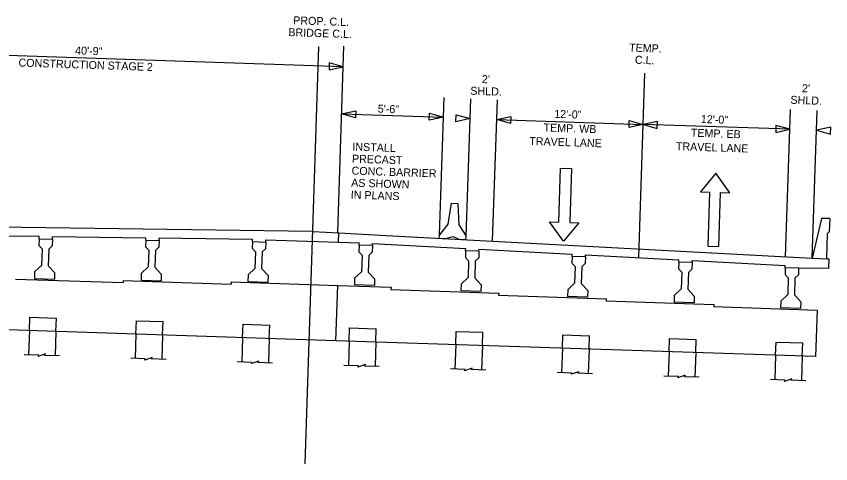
# Model space of a CAD drawing. Extents: x 977258 to 978774, y 1525947 to 1526932.
# Drawn here: x 977645 to 978256, y 1526136 to 1526472 of the extents above; entities that cross this region are included whole.
import ezdxf

# ---------------------------------------------------------------- set-up
doc = ezdxf.new("R2010")
doc.units = 0
for name, color, linetype in [('B_County and Route', 7, 'Continuous'), ('BDR_Plan Profile Grid 1', 7, 'Continuous'), ('BDR_Plan Profile Grid 5', 7, 'Continuous'), ('BDR_Plan Profile Grid 6', 7, 'Continuous'), ('Default', 7, 'Continuous'), ('R_Border', 7, 'Continuous'), ('R_MOT', 7, 'Continuous'), ('STAMP_PP', 7, 'Continuous')]:
    doc.layers.add(name, color=color, linetype=linetype)

msp = doc.modelspace()

# ---------------------------------------------------------------- linework, layer by layer
at = {"layer": 'B_County and Route'}
for p, q in [((977861.48, 1526136.32), (977871.91, 1526449.32)), ((978111.78, 1526291.34), (978116.39, 1526429.43))]:
    msp.add_line(p, q, dxfattribs=at)
at = {"layer": 'BDR_Plan Profile Grid 1'}
for p, q in [((977661.69, 1526217.73), (977650.75, 1526218.1)), ((977666.88, 1526218.68), (977661.27, 1526216.79)), ((977661.27, 1526216.79), (977661.69, 1526217.73)), ((977666.18, 1526217.58), (977666.88, 1526218.68)), ((977677.24, 1526217.21), (977666.18, 1526217.58)), ((977741.64, 1526215.07), (977730.71, 1526215.43)), ((977746.84, 1526216.01), (977741.23, 1526214.12)), ((977741.23, 1526214.12), (977741.64, 1526215.07)), ((977746.14, 1526214.92), (977746.84, 1526216.01)), ((977757.2, 1526214.55), (977746.14, 1526214.92)), ((977821.6, 1526212.4), (977810.67, 1526212.76)), ((977826.79, 1526213.35), (977821.18, 1526211.45)), ((977821.18, 1526211.45), (977821.6, 1526212.4)), ((977826.09, 1526212.25), (977826.79, 1526213.35)), ((977837.15, 1526211.88), (977826.09, 1526212.25))]:
    msp.add_line(p, q, dxfattribs=at)
at = {"layer": 'BDR_Plan Profile Grid 5'}
for p, q in [((977867.29, 1526310.65), (977492.25, 1526315.66)), ((978248.66, 1526320.45), (978241.83, 1526290.66)), ((978254.91, 1526320.24), (978248.66, 1526320.45)), ((978254.91, 1526320.24), (978254.57, 1526310.25)), ((977867.29, 1526310.65), (977886.74, 1526309.62)), ((977886.74, 1526309.62), (977922.22, 1526307.72)), ((978252.65, 1526290.08), (978253.28, 1526309.04)), ((978254.57, 1526310.25), (978253.28, 1526309.04)), ((977662.04, 1526306.73), (977592.03, 1526307.66)), ((977661.99, 1526305.16), (977661.82, 1526300.16)), ((977661.99, 1526305.16), (977661.82, 1526300.16)), ((977661.99, 1526305.16), (977662.04, 1526306.73)), ((977661.99, 1526305.16), (977671.98, 1526304.83)), ((977661.99, 1526305.16), (977671.98, 1526304.83)), ((977671.98, 1526304.83), (977671.82, 1526299.83)), ((977671.98, 1526304.83), (977671.82, 1526299.83)), ((977671.98, 1526304.83), (977671.82, 1526299.83)), ((977671.98, 1526304.83), (977671.82, 1526299.83)), ((977671.98, 1526304.83), (977672.04, 1526306.59)), ((977742.05, 1526305.66), (977672.04, 1526306.59)), ((977742, 1526304.09), (977741.83, 1526299.1)), ((977742, 1526304.09), (977741.83, 1526299.1)), ((977742, 1526304.09), (977742.05, 1526305.66)), ((977742, 1526304.09), (977751.99, 1526303.76)), ((977742, 1526304.09), (977751.99, 1526303.76)), ((977751.99, 1526303.76), (977751.83, 1526298.76)), ((977751.99, 1526303.76), (977751.83, 1526298.76)), ((977751.99, 1526303.76), (977751.83, 1526298.76)), ((977751.99, 1526303.76), (977751.83, 1526298.76)), ((977751.99, 1526303.76), (977752.05, 1526305.53)), ((977822.06, 1526304.59), (977752.05, 1526305.53)), ((977822.01, 1526303.03), (977821.84, 1526298.03)), ((977822.01, 1526303.03), (977821.84, 1526298.03)), ((977822.01, 1526303.03), (977822.06, 1526304.59)), ((977822.01, 1526303.03), (977832, 1526302.69)), ((977822.01, 1526303.03), (977832, 1526302.69)), ((977832, 1526302.69), (977831.84, 1526297.7)), ((977832, 1526302.69), (977831.84, 1526297.7)), ((977832, 1526302.69), (977831.84, 1526297.7)), ((977832, 1526302.69), (977831.84, 1526297.7)), ((977832, 1526302.69), (977832.06, 1526304.46)), ((977832.06, 1526304.46), (977886.51, 1526302.64)), ((977886.51, 1526302.64), (977902.02, 1526302.12)), ((977922.22, 1526307.72), (978241.83, 1526290.66)), ((977661.82, 1526300.16), (977664.24, 1526297.58)), ((977661.82, 1526300.16), (977664.24, 1526297.58)), ((977664.24, 1526297.58), (977663.82, 1526285.09)), ((977664.24, 1526297.58), (977663.82, 1526285.09)), ((977669.24, 1526297.41), (977668.82, 1526284.92)), ((977669.24, 1526297.41), (977668.82, 1526284.92)), ((977671.82, 1526299.83), (977669.24, 1526297.41)), ((977671.82, 1526299.83), (977669.24, 1526297.41)), ((977741.83, 1526299.1), (977744.25, 1526296.51)), ((977741.83, 1526299.1), (977744.25, 1526296.51)), ((977744.25, 1526296.51), (977743.83, 1526284.02)), ((977744.25, 1526296.51), (977743.83, 1526284.02)), ((977749.25, 1526296.35), (977748.83, 1526283.85)), ((977749.25, 1526296.35), (977748.83, 1526283.85)), ((977751.83, 1526298.76), (977749.25, 1526296.35)), ((977751.83, 1526298.76), (977749.25, 1526296.35)), ((977821.84, 1526298.03), (977824.26, 1526295.45)), ((977821.84, 1526298.03), (977824.26, 1526295.45)), ((977831.84, 1526297.7), (977829.25, 1526295.28)), ((977831.84, 1526297.7), (977829.25, 1526295.28)), ((977901.97, 1526300.36), (977901.8, 1526295.36)), ((977901.97, 1526300.36), (977901.8, 1526295.36)), ((977901.97, 1526300.36), (977902.02, 1526302.12)), ((977911.96, 1526300.03), (977901.97, 1526300.36)), ((977911.96, 1526300.03), (977911.79, 1526295.03)), ((977911.96, 1526300.03), (977912.01, 1526301.59)), ((977912.01, 1526301.59), (977981.93, 1526297.86)), ((977981.87, 1526296.09), (977981.93, 1526297.86)), ((977991.86, 1526295.76), (977991.91, 1526297.33)), ((977991.91, 1526297.33), (978061.83, 1526293.59)), ((977824.26, 1526295.45), (977823.84, 1526282.95)), ((977824.26, 1526295.45), (977823.84, 1526282.95)), ((977829.25, 1526295.28), (977828.84, 1526282.79)), ((977829.25, 1526295.28), (977828.84, 1526282.79)), ((977901.8, 1526295.36), (977904.21, 1526292.78)), ((977904.21, 1526292.78), (977903.8, 1526280.29)), ((977909.21, 1526292.61), (977908.8, 1526280.12)), ((977911.79, 1526295.03), (977909.21, 1526292.61)), ((977981.87, 1526296.09), (977981.7, 1526291.1)), ((977981.87, 1526296.09), (977981.7, 1526291.1)), ((977981.7, 1526291.1), (977984.12, 1526288.51)), ((977991.86, 1526295.76), (977981.87, 1526296.09)), ((977991.7, 1526290.76), (977989.11, 1526288.35)), ((977991.86, 1526295.76), (977991.7, 1526290.76)), ((978061.77, 1526291.83), (978061.6, 1526286.83)), ((978061.77, 1526291.83), (978061.6, 1526286.83)), ((978061.77, 1526291.83), (978061.83, 1526293.59)), ((978071.76, 1526291.5), (978061.77, 1526291.83)), ((978071.76, 1526291.5), (978071.6, 1526286.5)), ((978071.76, 1526291.5), (978071.82, 1526293.06)), ((978071.82, 1526293.06), (978141.73, 1526289.33)), ((978252.65, 1526290.08), (978254.31, 1526289.99)), ((977658.66, 1526280.26), (977663.82, 1526285.09)), ((977658.66, 1526280.26), (977663.82, 1526285.09)), ((977673.65, 1526279.76), (977668.82, 1526284.92)), ((977673.65, 1526279.76), (977668.82, 1526284.92)), ((977738.67, 1526279.19), (977743.83, 1526284.02)), ((977738.67, 1526279.19), (977743.83, 1526284.02)), ((977984.12, 1526288.51), (977983.7, 1526276.02)), ((977989.11, 1526288.35), (977988.7, 1526275.86)), ((978061.6, 1526286.83), (978064.02, 1526284.25)), ((978064.02, 1526284.25), (978063.6, 1526271.76)), ((978069.02, 1526284.08), (978068.6, 1526271.59)), ((978071.6, 1526286.5), (978069.02, 1526284.08)), ((978141.67, 1526287.56), (978141.51, 1526282.57)), ((978141.67, 1526287.56), (978141.51, 1526282.57)), ((978141.67, 1526287.56), (978141.73, 1526289.33)), ((978151.67, 1526287.23), (978141.67, 1526287.56)), ((978151.67, 1526287.23), (978151.5, 1526282.23)), ((978151.67, 1526287.23), (978151.72, 1526288.8)), ((978151.72, 1526288.8), (978221.63, 1526285.06)), ((978221.57, 1526283.3), (978221.63, 1526285.06)), ((978254.31, 1526289.99), (978254.07, 1526282.71)), ((977658.66, 1526280.26), (977658.49, 1526275.26)), ((977658.66, 1526280.26), (977658.49, 1526275.26)), ((977673.65, 1526279.76), (977673.48, 1526274.76)), ((977673.65, 1526279.76), (977673.48, 1526274.76)), ((977738.67, 1526279.19), (977738.5, 1526274.19)), ((977738.67, 1526279.19), (977738.5, 1526274.19)), ((977753.66, 1526278.69), (977748.83, 1526283.85)), ((977753.66, 1526278.69), (977748.83, 1526283.85)), ((977753.66, 1526278.69), (977753.49, 1526273.69)), ((977753.66, 1526278.69), (977753.49, 1526273.69)), ((977818.68, 1526278.12), (977818.51, 1526273.13)), ((977818.68, 1526278.12), (977818.51, 1526273.13)), ((977818.68, 1526278.12), (977823.84, 1526282.95)), ((977818.68, 1526278.12), (977823.84, 1526282.95)), ((977833.67, 1526277.62), (977828.84, 1526282.79)), ((977833.67, 1526277.62), (977828.84, 1526282.79)), ((977898.63, 1526275.46), (977903.8, 1526280.29)), ((977913.63, 1526274.96), (977908.8, 1526280.12)), ((978141.51, 1526282.57), (978143.92, 1526279.98)), ((978143.92, 1526279.98), (978143.5, 1526267.49)), ((978148.92, 1526279.82), (978148.5, 1526267.32)), ((978151.5, 1526282.23), (978148.92, 1526279.82)), ((978221.57, 1526283.3), (978221.41, 1526278.3)), ((978221.57, 1526283.3), (978221.41, 1526278.3)), ((978221.41, 1526278.3), (978223.82, 1526275.72)), ((978231.57, 1526282.96), (978221.57, 1526283.3)), ((978231.4, 1526277.97), (978228.82, 1526275.55)), ((978231.57, 1526282.96), (978231.4, 1526277.97)), ((978254.07, 1526282.71), (978231.57, 1526282.96)), ((977644.31, 1526274.9), (977725.1, 1526272.21)), ((977658.49, 1526275.26), (977673.48, 1526274.76)), ((977658.49, 1526275.26), (977673.48, 1526274.76)), ((977725.15, 1526273.8), (977725.1, 1526272.21)), ((977725.15, 1526273.8), (977805.94, 1526271.11)), ((977738.5, 1526274.19), (977753.49, 1526273.69)), ((977738.5, 1526274.19), (977753.49, 1526273.69)), ((977805.99, 1526272.71), (977805.94, 1526271.11)), ((977805.99, 1526272.71), (977885.94, 1526270.04)), ((977818.51, 1526273.13), (977833.5, 1526272.63)), ((977818.51, 1526273.13), (977833.5, 1526272.63)), ((977833.67, 1526277.62), (977833.5, 1526272.63)), ((977833.67, 1526277.62), (977833.5, 1526272.63)), ((977898.63, 1526275.46), (977898.47, 1526270.46)), ((977913.63, 1526274.96), (977913.46, 1526269.96)), ((977978.54, 1526271.19), (977983.7, 1526276.02)), ((977993.53, 1526270.69), (977988.7, 1526275.86)), ((978058.44, 1526266.93), (978063.6, 1526271.76)), ((978223.82, 1526275.72), (978223.41, 1526263.23)), ((978228.82, 1526275.55), (978228.4, 1526263.06)), ((977884.56, 1526228.67), (977885.94, 1526270.04)), ((977885.94, 1526270.04), (977925.92, 1526268.71)), ((977913.46, 1526269.96), (977898.47, 1526270.46)), ((977925.92, 1526268.71), (977925.87, 1526267.11)), ((977925.87, 1526267.11), (978006.66, 1526264.42)), ((977978.54, 1526271.19), (977978.37, 1526266.19)), ((977993.36, 1526265.69), (977978.37, 1526266.19)), ((977993.53, 1526270.69), (977993.36, 1526265.69)), ((978058.44, 1526266.93), (978058.27, 1526261.93)), ((978073.43, 1526266.43), (978068.6, 1526271.59)), ((978073.43, 1526266.43), (978073.26, 1526261.43)), ((978138.34, 1526262.66), (978143.5, 1526267.49)), ((978153.33, 1526262.16), (978148.5, 1526267.32)), ((978006.66, 1526264.42), (978006.6, 1526262.82)), ((978006.6, 1526262.82), (978087.39, 1526260.12)), ((978073.26, 1526261.43), (978058.27, 1526261.93)), ((978087.39, 1526260.12), (978087.34, 1526258.52)), ((978138.34, 1526262.66), (978138.17, 1526257.66)), ((978153.33, 1526262.16), (978153.17, 1526257.16)), ((978218.24, 1526258.39), (978223.41, 1526263.23)), ((978233.23, 1526257.89), (978228.4, 1526263.06)), ((978087.34, 1526258.52), (978168.13, 1526255.83)), ((978153.17, 1526257.16), (978138.17, 1526257.66)), ((978168.13, 1526255.83), (978168.07, 1526254.23)), ((978168.07, 1526254.23), (978245.53, 1526251.65)), ((978218.24, 1526258.39), (978218.08, 1526253.4)), ((978233.23, 1526257.89), (978233.07, 1526252.9)), ((978233.07, 1526252.9), (978218.08, 1526253.4)), ((978245.53, 1526251.65), (978244.36, 1526216.67)), ((977884.56, 1526228.67), (977484.79, 1526242)), ((977654.69, 1526236.33), (977654.08, 1526217.99)), ((977674.68, 1526235.67), (977674.07, 1526217.32)), ((977734.65, 1526233.67), (977734.04, 1526215.32)), ((977754.64, 1526233), (977754.03, 1526214.65)), ((977814.6, 1526231), (977813.99, 1526212.65)), ((977834.59, 1526230.33), (977833.98, 1526211.99)), ((978244.36, 1526216.67), (977884.56, 1526228.67)), ((977894.56, 1526228.33), (977893.95, 1526209.99)), ((977914.55, 1526227.67), (977913.94, 1526209.32)), ((977974.51, 1526225.67), (977973.9, 1526207.32)), ((977994.5, 1526225), (977993.89, 1526206.65)), ((978054.47, 1526223), (978053.86, 1526204.65)), ((978074.46, 1526222.33), (978073.85, 1526203.99)), ((978134.43, 1526220.33), (978133.81, 1526201.99)), ((978154.41, 1526219.67), (978153.8, 1526201.32)), ((978214.38, 1526217.67), (978213.77, 1526199.32)), ((978234.37, 1526217), (978233.76, 1526198.66)), ((977906.75, 1526210.68), (977901.14, 1526208.79)), ((977906.05, 1526209.58), (977906.75, 1526210.68)), ((977901.56, 1526209.73), (977890.62, 1526210.1)), ((977901.14, 1526208.79), (977901.56, 1526209.73)), ((977917.11, 1526209.21), (977906.05, 1526209.58)), ((977981.51, 1526207.07), (977970.58, 1526207.43)), ((977986.71, 1526208.02), (977981.09, 1526206.12)), ((977981.09, 1526206.12), (977981.51, 1526207.07)), ((977986, 1526206.92), (977986.71, 1526208.02)), ((977997.06, 1526206.55), (977986, 1526206.92)), ((978061.47, 1526204.4), (978050.53, 1526204.77)), ((978066.66, 1526205.35), (978061.05, 1526203.45)), ((978065.96, 1526204.25), (978066.66, 1526205.35)), ((978061.05, 1526203.45), (978061.47, 1526204.4)), ((978077.02, 1526203.88), (978065.96, 1526204.25)), ((978141.42, 1526201.73), (978130.49, 1526202.1)), ((978146.62, 1526202.68), (978141.01, 1526200.79)), ((978141.01, 1526200.79), (978141.42, 1526201.73)), ((978145.91, 1526201.58), (978146.62, 1526202.68)), ((978156.98, 1526201.22), (978145.91, 1526201.58)), ((978221.38, 1526199.07), (978210.44, 1526199.43)), ((978226.57, 1526200.02), (978220.96, 1526198.12)), ((978220.96, 1526198.12), (978221.38, 1526199.07)), ((978225.87, 1526198.92), (978226.57, 1526200.02)), ((978236.93, 1526198.55), (978225.87, 1526198.92))]:
    msp.add_line(p, q, dxfattribs=at)
at = {"layer": 'BDR_Plan Profile Grid 6'}
for p, q in [((977886.51, 1526302.64), (977886.74, 1526309.62)), ((978241.83, 1526290.66), (978252.65, 1526290.08)), ((977654.69, 1526236.33), (977655.03, 1526246.33)), ((977655.03, 1526246.33), (977675.01, 1526245.66)), ((977674.68, 1526235.67), (977675.01, 1526245.66)), ((977734.65, 1526233.67), (977734.98, 1526243.66)), ((977734.98, 1526243.66), (977754.97, 1526242.99)), ((977754.64, 1526233), (977754.97, 1526242.99)), ((977814.6, 1526231), (977814.94, 1526240.99)), ((977814.94, 1526240.99), (977834.93, 1526240.33)), ((977834.59, 1526230.33), (977834.93, 1526240.33)), ((977894.56, 1526228.33), (977894.89, 1526238.33)), ((977894.89, 1526238.33), (977914.88, 1526237.66)), ((977914.55, 1526227.67), (977914.88, 1526237.66)), ((977974.51, 1526225.67), (977974.85, 1526235.66)), ((977974.85, 1526235.66), (977994.84, 1526234.99)), ((977994.5, 1526225), (977994.84, 1526234.99)), ((978054.47, 1526223), (978054.8, 1526232.99)), ((978054.8, 1526232.99), (978074.79, 1526232.33)), ((978074.46, 1526222.33), (978074.79, 1526232.33)), ((978134.43, 1526220.33), (978134.76, 1526230.33)), ((978134.76, 1526230.33), (978154.75, 1526229.66)), ((978154.41, 1526219.67), (978154.75, 1526229.66)), ((978214.38, 1526217.67), (978214.71, 1526227.66)), ((978214.71, 1526227.66), (978234.7, 1526227)), ((978234.37, 1526217), (978234.7, 1526227))]:
    msp.add_line(p, q, dxfattribs=at)
at = {"layer": 'Default'}
for points in [[(978066.8, 1526317.21), (978055.33, 1526303.31), (978044.82, 1526317.95), (978051.69, 1526317.72), (978053.04, 1526358.15), (978061.28, 1526357.88), (978059.93, 1526317.44)], [(978179.94, 1526339.63), (978169.42, 1526354.27), (978157.95, 1526340.37), (978164.82, 1526340.14), (978163.47, 1526299.7), (978171.72, 1526299.43), (978173.07, 1526339.86)]]:
    msp.add_lwpolyline(points, close=True, dxfattribs=at)
at = {"layer": 'R_MOT'}
for p, q in [((977971.06, 1526331.87), (977968.55, 1526316.14)), ((977971.06, 1526331.87), (977971.03, 1526331.29)), ((977971.06, 1526331.87), (977976.05, 1526331.6)), ((977976.05, 1526331.6), (977976.87, 1526315.7)), ((977968.55, 1526316.14), (977962.28, 1526308.13)), ((977976.87, 1526315.7), (977982.25, 1526307.07)), ((977962.15, 1526305.64), (977962.28, 1526308.13)), ((977962.15, 1526305.64), (977962.15, 1526305.64)), ((977962.15, 1526305.64), (977967.14, 1526305.37)), ((977967.14, 1526305.37), (977972.22, 1526306.77)), ((977972.22, 1526306.77), (977977.13, 1526304.84)), ((977977.13, 1526304.84), (977982.12, 1526304.57)), ((977982.12, 1526304.57), (977982.25, 1526307.07))]:
    msp.add_line(p, q, dxfattribs=at)
at = {"layer": 'STAMP_PP'}
for p, q in [((977885.94, 1526310.03), (977890.6, 1526449.76)), ((977890.08, 1526434.2), (977484.14, 1526447.74)), ((977962.28, 1526308.13), (977965.72, 1526411.15)), ((977982.23, 1526307.1), (977985.67, 1526410.11)), ((978002.12, 1526303.46), (978005.66, 1526409.45)), ((978221.85, 1526291.73), (978225.54, 1526402.12)), ((978241.83, 1526290.66), (978245.52, 1526401.45)), ((977888.91, 1526398.86), (977965.22, 1526396.31)), ((978005.16, 1526394.61), (978115.1, 1526390.95)), ((978225.04, 1526387.28), (978115.1, 1526390.95))]:
    msp.add_line(p, q, dxfattribs=at)
for points in [[(977879.44, 1526431.91), (977890.08, 1526434.2), (977879.62, 1526437.19)], [(977899.37, 1526395.87), (977888.91, 1526398.86), (977899.55, 1526401.14)], [(977954.76, 1526399.3), (977965.22, 1526396.31), (977954.58, 1526394.03)], [(977974.71, 1526398.27), (977985.17, 1526395.28), (977974.53, 1526392.99)], [(978015.63, 1526391.62), (978005.16, 1526394.61), (978015.81, 1526396.9)], [(978104.64, 1526393.94), (978115.1, 1526390.95), (978104.46, 1526388.66)], [(978125.74, 1526393.23), (978115.1, 1526390.95), (978125.57, 1526387.96)], [(978214.4, 1526384.99), (978225.04, 1526387.28), (978214.57, 1526390.27)], [(978255.67, 1526388.9), (978245.03, 1526386.61), (978255.5, 1526383.62)]]:
    msp.add_lwpolyline(points, close=True, dxfattribs=at)

# ---------------------------------------------------------------- texts
at = {"layer": 'R_Border'}
for s, p in [('PROP. C.L.', (977852.5, 1526466.14)), ('BRIDGE C.L.', (977848.85, 1526457.26)), ('40\'-9"', (977688.95, 1526443.52)), ('TEMP.', (978104.37, 1526445.68)), ('CONSTRUCTION STAGE 2', (977646.48, 1526434.43)), ('C.L.', (978108.75, 1526436.53)), ("2' ", (977993.96, 1526422.01)), ('SHLD.', (977985.3, 1526413.3)), ("2' ", (978234.06, 1526415.18)), ('SHLD.', (978225.4, 1526406.47)), ('5\'-6"', (977915.92, 1526399.83)), ('12\'-0"', (978048.26, 1526395.96)), ('12\'-0"', (978158.19, 1526392.05)), ('TEMP. WB', (978040.21, 1526385.73)), ('TEMP. EB', (978150.66, 1526381.8)), ('INSTALL ', (977896.87, 1526371.31)), ('TRAVEL LANE', (978029.54, 1526375.58)), ('TRAVEL LANE', (978139.47, 1526371.67)), ('PRECAST', (977896.57, 1526362.31)), ('CONC. BARRIER', (977896.27, 1526353.32)), ('AS SHOWN ', (977895.97, 1526344.32)), ('IN PLANS', (977895.67, 1526335.33))]:
    msp.add_text(s, height=6, rotation=358.09005, dxfattribs=at).set_placement(p)

doc.saveas('drawing.dxf')
